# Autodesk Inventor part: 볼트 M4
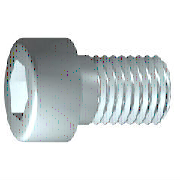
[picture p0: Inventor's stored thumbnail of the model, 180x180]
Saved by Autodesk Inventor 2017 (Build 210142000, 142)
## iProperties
IsCustomPart: 0
Created: 2012-02
Part Number: 볼트 M4
Material: 스테인리스강
Description: 6각 소켓 머리 캡 나사
Document SubType Name: Modeling
Standard: ISO 4762
Designer: mduedu
Standard Revision: Fourth edition 2004-03-01
Standards Organization: ISO
Language: ko-KR
Size Designation: M4 x 12
Categories: <MemberInstance><Categories><Category DisplayName="조임쇠" InternalName="e4da775c-781d-43d5-af7c-5136215cf5a6" Mnemonic="FSTN"><Category DisplayName="볼트" InternalN
Density: 8.08 g/cm^3
Appearance: 반광택
Author: mduedu
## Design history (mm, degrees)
sketch "스케치1"
  geometry: L1 (-1, 0)-(12, 0); L2 (12, 0)-(12, 2); L3 (12, 2)-(1.75, 2); L4 (1.75, 2)-(1.32, 2); L5 (1.32, 2)-(0, 2); L6 (0, 2)-(0, 3.5); L7 (0, 3.5)-(-4, 3.5); L8 (-4, 3.5)-(-4, 1.732); L9 (-4, 1.732)-(-2, 1.732); L10 (-2, 1.732)-(-1, 0); L11 (-7.2, 0)-(15.2, 0) reference; L12 (0, -0.7)-(0, 4.2) reference; L13 (1.75, 2)-(0, 2)
  constraints: 22 end point, 6 parallel, 2 collinear, 2 perpendicular, 1 horizontal, 1 point on line
  dimensions: "d1" = 10.25 distance from line of L3.end L2 (= GEL); "d2" = 0.42952 distance of L4.end L3.end (computed from GAL); "d3" = 4 distance between parallel lines of L8 L6 (= KOH); "d4" = 2 distance of L8.end L9.end (= INTI); "d5" = 60 deg angle of L10 L1; "d6" = 4 diameter of L3 L1 (= GD); "d7" = 4 diameter of L5 L1 (= BDM); "d8" = 3.4641 diameter of L9 L1 (= 1.1547 x SW); "d9" = 7 diameter of L7 L1 (= KOD); "d26" = 12 distance between parallel lines of L12 L2 (= NLG)
revolve "본체" sketch "스케치1" stored, may be unused: angle "d10" = 90 deg
sketch "스케치2"
  geometry: L1 (0, -4.9)-(0, 4.9) reference; L2 (-4.9, 0)-(4.9, 0) reference; L3 (1.732, 0)-(0.866, -1.5); L4 (0.866, -1.5)-(-0.866, -1.5); L5 (-0.866, -1.5)-(-1.732, 0); L6 (-1.732, 0)-(-0.866, 1.5); L7 (-0.866, 1.5)-(0.866, 1.5); L8 (0.866, 1.5)-(1.732, 0); 2 further points
  constraints: 12 end point, 1 coincident, 1 horizontal alignment, 1 point on line, 12 other
extrude "슬롯" join sketch "스케치2" stored distance "d11" = 10; taper "d12" = 0 deg
workplane "Work Plane1"
fillet "Fillet2" dims "d30" = 0.1 (= R)
body "Solid1"
fillet "모깎기1" dims "d17" = 0.4 (= RR)
feature "스레드" dims "d13" = 10.25 (= GEL), "d14" = 0
chamfer "모따기1" distance "d15" = 0.42941 (= -0.5 x SPD + 0.5 x GD); stored, may be unused: second distance "d16" = 0.42941 (= GUL), angle "d27" = 45 deg
other parameters: "GD" = 4 [user parameter; used in 2 equation terms], "NLG" = 12 [user parameter; used in 1 equation term], "GEL" = 10.25 [user parameter; used in 2 equation terms], "KOD" = 7 [user parameter; used in 1 equation term], "KOH" = 4 [user parameter; used in 1 equation term], "INTI" = 2 [user parameter; used in 1 equation term], "GAL" = 0.42941 (= 0.61345 x PTC) [user parameter; used in 1 equation term], "GUL" = 0.42941 (= 0.61345 x PTC) [user parameter; used in 1 equation term], "BDM" = 4 (= NND) [user parameter; used in 1 equation term], "SW" = 3 [user parameter; used in 2 equation terms], "RR" = 0.4 [user parameter; used in 1 equation term], "SPD" = 3.14117 (= NND - 1.2269 x PTC) [user parameter; used in 1 equation term], "d19" = 0, "d28" = 0, "d29" = 0, "R" = 0.1 [user parameter; used in 1 equation term], "TOA" = 30 deg [user parameter], "GD1" = 3.14117 (= THREADDIA - 1.2269 x PTC) [user parameter], "THREADDIA" = 4 [user parameter; used in 1 equation term], "FAWI" = 45 deg [user parameter], "TPU" = 14.28571 (computed from PTC) [user parameter], "PTC" = 0.7 [user parameter; used in 5 equation terms], "NND" = 4 [user parameter; used in 2 equation terms], "E0" = 3.465 (= 1.155 x SW) [user parameter]
